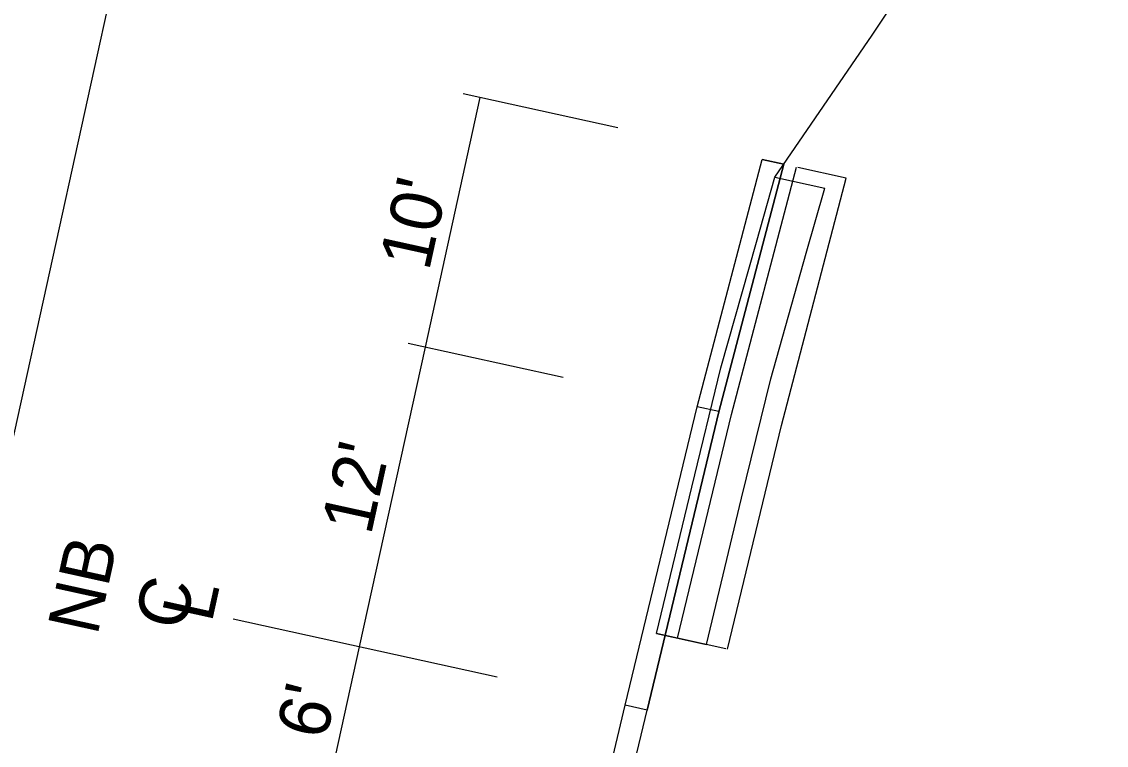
# Model space of a CAD drawing. Extents: x 14104283 to 14120882, y 8635219 to 8671666.
# Drawn here: x 14106777.1 to 14106946.9, y 8639634.3 to 8639747.5 of the extents above; entities that cross this region are included whole.
import ezdxf

# ---------------------------------------------------------------- set-up
doc = ezdxf.new("R2010")
doc.units = 0
for name, color, linetype in [('dsnShadingPaved', 7, 'Continuous'), ('dsnTextFinalPlan', 7, 'Continuous'), ('dsnTextOverlapEven', 7, 'Continuous'), ('TC_ShoulderPCC', 7, 'Continuous'), ('TC_Subbase', 7, 'Continuous'), ('TC_SubgradeTreatment', 7, 'Continuous'), ('TC_SubstrataExistingPavement', 7, 'Continuous'), ('Terrain', 7, 'Continuous')]:
    doc.layers.add(name, color=color, linetype=linetype)

msp = doc.modelspace()

# ---------------------------------------------------------------- linework, layer by layer
at = {"layer": 'dsnShadingPaved'}
msp.add_lwpolyline([(14106871.61, 8639640.57), (14106882.86, 8639687.25), (14106893.02, 8639725.96), (14106896.44, 8639725.21), (14106886.27, 8639686.49), (14106875.03, 8639639.81)], close=True, dxfattribs=at)
at = {"layer": 'dsnTextFinalPlan'}
for p, q in [((14106840.32, 8639696.58), (14106848.91, 8639735.65)), ((14106870.46, 8639730.92), (14106846.24, 8639736.24)), ((14106830.02, 8639649.7), (14106840.32, 8639696.58)), ((14106861.88, 8639691.85), (14106837.65, 8639697.17)), ((14106851.57, 8639644.97), (14106810.24, 8639654.05)), ((14106824.87, 8639626.26), (14106830.02, 8639649.7))]:
    msp.add_line(p, q, dxfattribs=at)
msp.add_lwpolyline([(14106628.13, 8639010.26), (14106841.8, 8639982.68), (14107038.61, 8639939.44), (14106824.95, 8638967.01)], close=True, dxfattribs=at)
at = {"layer": 'dsnTextOverlapEven'}
msp.add_lwpolyline([(14106628.13, 8639010.26), (14106841.8, 8639982.68), (14107038.61, 8639939.44), (14106824.95, 8638967.01)], close=True, dxfattribs=at)
at = {"layer": 'TC_ShoulderPCC'}
for p, q in [((14106882.86, 8639687.25), (14106893.02, 8639725.96)), ((14106886.27, 8639686.49), (14106896.44, 8639725.21)), ((14106896.44, 8639725.21), (14106893.02, 8639725.96)), ((14106871.61, 8639640.57), (14106882.86, 8639687.25)), ((14106886.28, 8639686.5), (14106882.86, 8639687.25)), ((14106875.03, 8639639.81), (14106886.27, 8639686.49)), ((14106875.03, 8639639.81), (14106871.61, 8639640.57))]:
    msp.add_line(p, q, dxfattribs=at)
at = {"layer": 'TC_Subbase'}
for p, q in [((14106888.23, 8639686.06), (14106898.39, 8639724.78)), ((14106879.79, 8639651.05), (14106888.23, 8639686.06)), ((14106875.03, 8639639.81), (14106877.84, 8639651.48)), ((14106879.79, 8639651.05), (14106876.5, 8639651.78))]:
    msp.add_line(p, q, dxfattribs=at)
at = {"layer": 'TC_SubgradeTreatment'}
for p, q in [((14106906.2, 8639723.06), (14106898.63, 8639724.73)), ((14106896.04, 8639684.34), (14106906.2, 8639723.06)), ((14106887.6, 8639649.34), (14106896.04, 8639684.34)), ((14106887.37, 8639649.39), (14106879.79, 8639651.05))]:
    msp.add_line(p, q, dxfattribs=at)
at = {"layer": 'TC_SubstrataExistingPavement'}
for p, q in [((14106895.04, 8639723.19), (14106902.85, 8639721.48)), ((14106876.5, 8639651.78), (14106884.32, 8639650.06)), ((14106863.78, 8639593.14), (14106875.03, 8639639.81))]:
    msp.add_line(p, q, dxfattribs=at)
msp.add_lwpolyline([(14106884.32, 8639650.06), (14106889.83, 8639672.95), (14106894.4, 8639691.63), (14106899.94, 8639711.28), (14106902.85, 8639721.48)], dxfattribs=at)
at = {"layer": 'Terrain'}
msp.add_line((14106860.36, 8639593.88), (14106871.61, 8639640.57), dxfattribs=at)
msp.add_lwpolyline([(14106876.5, 8639651.78), (14106882.01, 8639674.67), (14106886.59, 8639693.34), (14106892.13, 8639713), (14106895.04, 8639723.19), (14106910.27, 8639745.39), (14106912.74, 8639749.15), (14106915.04, 8639754.38), (14106922.48, 8639770.34), (14106925.07, 8639778.64), (14106926.9, 8639784.51), (14106935.67, 8639818.68), (14106936.11, 8639820.55), (14106942.98, 8639834.9), (14106944.19, 8639837.6), (14106943.22, 8639843.23), (14106939.5, 8639862.53), (14106936.96, 8639872.94), (14106934.15, 8639884.43), (14106935.67, 8639891.08), (14106936.54, 8639894.64), (14106936.01, 8639897.7), (14106934.23, 8639909.05), (14106935.48, 8639914.49)], dxfattribs=at)

# ---------------------------------------------------------------- texts
at = {"layer": 'dsnTextFinalPlan'}
for s, p in [("10'", (14106840.88, 8639708.34)), ("12'", (14106831.79, 8639667)), ('NB', (14106788.97, 8639651.31)), ('C', (14106802.61, 8639652.02)), ('L', (14106806.87, 8639653.32)), ("6'", (14106824.76, 8639634.98))]:
    msp.add_text(s, height=8, rotation=77.6078, dxfattribs=at).set_placement(p)

doc.saveas('drawing.dxf')
